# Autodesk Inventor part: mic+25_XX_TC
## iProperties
Shininess: 20.0
Length Units: 11269
Angle Units: 11279
Time Units: 11290
Mass Units: 11283
Length Display Precision: 2
Angle Display Precision: 2
Company: Microsonic
Part Number: mic+25_XX_TC
Material: ABS Plastik
Document SubType Name: Modellieren
Description: mic+ 25 Sensor
Checked By: Alves
Created: 2005-08
Designer: Ohle
Manufacturer: Standard
Standards Organization: Custom
Density: 0.0
Volumn: 0.0
Area: 0.0
PropertySet Name: Model Information
Control State: 0
Master: False
Checked Out: False
Last Check In By: Kramp
Last Check In Date: 2005-08-09
BESTELLNUMMER: mic+25/XX/TC
ME: ST
Title: mic+ 25 Sensor
Author: Ohle
Comments: keine Bemerkung
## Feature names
1. Grundkörper [Revolution]
2. Bohrung1 [Hole]
3. Pole [Extrusion]
4. Abrundung Pole [Fillet]
5. Verdrehsicherung [Extrusion]
